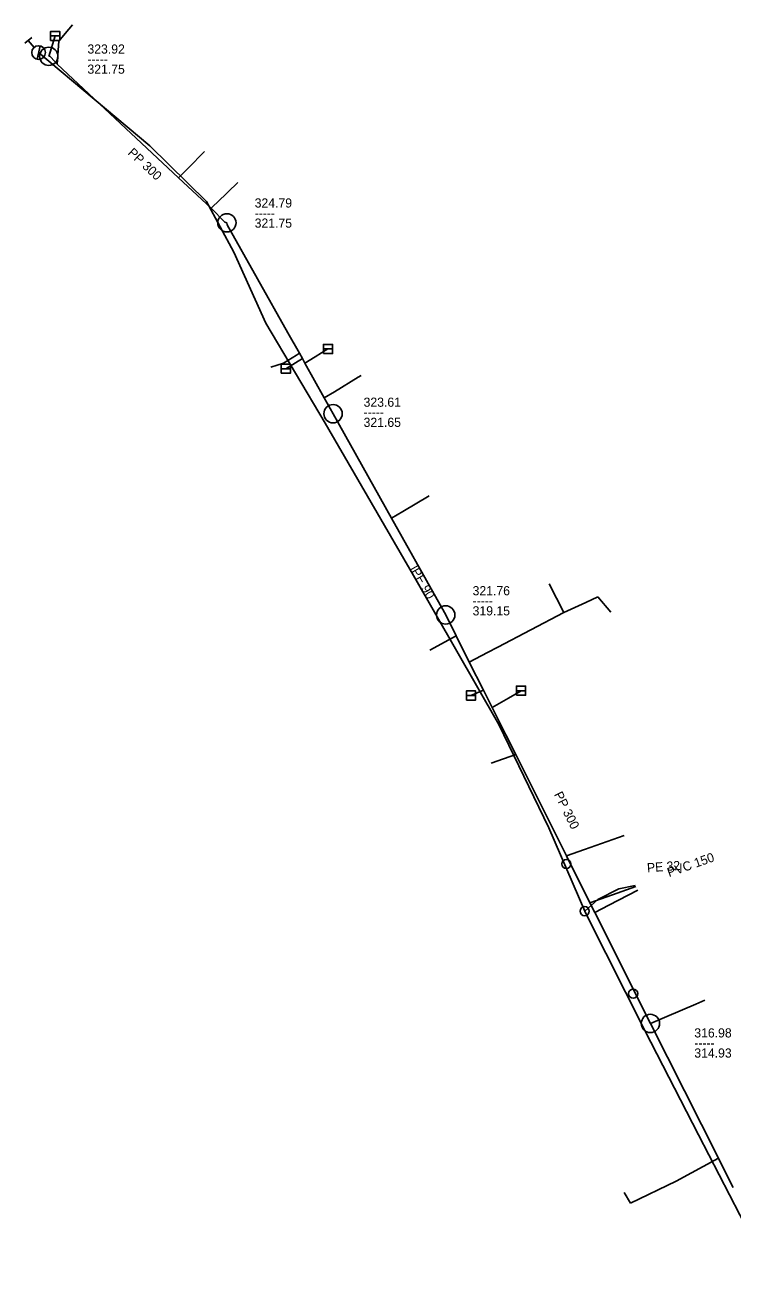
# Model space of a CAD drawing. Extents: x -770550 to -770198, y -1055065 to -1054790.
# Drawn here: x -770439.9 to -770362.5, y -1054925.1 to -1054789.6 of the extents above; entities that cross this region are included whole.
import ezdxf

# ---------------------------------------------------------------- set-up
doc = ezdxf.new("R2010")
doc.units = 0
doc.layers.add('Level 0', color=7, linetype='Continuous')

msp = doc.modelspace()

# ---------------------------------------------------------------- linework, layer by layer
at = {"layer": 'Level 0'}
for p, q in [((-770434.71, -1054789.58), (-770435.51, -1054790.52)), ((-770439.95, -1054791.6), (-770439.18, -1054790.96)), ((-770438.92, -1054792.05), (-770439.56, -1054791.28)), ((-770437.32, -1054793.03), (-770436.62, -1054790.8)), ((-770437.12, -1054790.8), (-770436.12, -1054790.8)), ((-770436.23, -1054791.37), (-770436.4, -1054793.88)), ((-770435.51, -1054790.52), (-770436.23, -1054791.37)), ((-770438.59, -1054793.35), (-770438.28, -1054791.88)), ((-770426.25, -1054802.83), (-770438.44, -1054792.62)), ((-770437.32, -1054793.03), (-770437.24, -1054792.96)), ((-770437.24, -1054792.96), (-770437.09, -1054793.13)), ((-770437.09, -1054793.13), (-770436.4, -1054793.88)), ((-770436.4, -1054793.88), (-770423.11, -1054806.3)), ((-770420.05, -1054808.91), (-770426.25, -1054802.83)), ((-770422.06, -1054805.24), (-770420.28, -1054803.43)), ((-770423.11, -1054806.3), (-770422.06, -1054805.24)), ((-770423.11, -1054806.3), (-770419.56, -1054809.62)), ((-770418.86, -1054808.96), (-770416.63, -1054806.84)), ((-770417.08, -1054814.45), (-770420.05, -1054808.91)), ((-770419.29, -1054809.36), (-770418.86, -1054808.96)), ((-770419.56, -1054809.62), (-770419.29, -1054809.36)), ((-770419.56, -1054809.62), (-770418.06, -1054811.17)), ((-770418.06, -1054811.17), (-770417.83, -1054811.23)), ((-770417.83, -1054811.23), (-770417.8, -1054811.46)), ((-770417.8, -1054811.46), (-770411.15, -1054823.26)), ((-770413.56, -1054822.19), (-770417.08, -1054814.45)), ((-770407.07, -1054833.15), (-770413.56, -1054822.19)), ((-770411.15, -1054823.26), (-770409.89, -1054825.49)), ((-770409.89, -1054825.49), (-770410.21, -1054825.69)), ((-770409.89, -1054825.49), (-770409.57, -1054826.07)), ((-770408.17, -1054825.87), (-770406.77, -1054825.02)), ((-770407.27, -1054825.02), (-770406.27, -1054825.02)), ((-770411.62, -1054826.58), (-770413.02, -1054827.01)), ((-770410.21, -1054825.69), (-770411.62, -1054826.58)), ((-770409.57, -1054826.07), (-770411.38, -1054827.18)), ((-770409.57, -1054826.07), (-770409.29, -1054826.56)), ((-770409.29, -1054826.56), (-770408.17, -1054825.87)), ((-770409.29, -1054826.56), (-770407.17, -1054830.37)), ((-770411.88, -1054827.18), (-770410.88, -1054827.18)), ((-770403.46, -1054828.11), (-770406.04, -1054829.69)), ((-770403.14, -1054827.92), (-770403.46, -1054828.11)), ((-770406.04, -1054829.69), (-770407.17, -1054830.37)), ((-770407.17, -1054830.37), (-770406.21, -1054832.1)), ((-770406.21, -1054832.1), (-770399.81, -1054843.52)), ((-770397.41, -1054849.79), (-770407.07, -1054833.15)), ((-770395.69, -1054841.08), (-770398.57, -1054842.78)), ((-770398.57, -1054842.78), (-770399.81, -1054843.52)), ((-770399.81, -1054843.52), (-770394.83, -1054852.41)), ((-770388.06, -1054866.07), (-770397.41, -1054849.79)), ((-770380.97, -1054853.84), (-770382.58, -1054850.71)), ((-770394.83, -1054852.41), (-770393.88, -1054854.1)), ((-770378.56, -1054852.74), (-770377.23, -1054852.11)), ((-770377.23, -1054852.11), (-770375.82, -1054853.8)), ((-770388.17, -1054857.61), (-770380.97, -1054853.84)), ((-770380.97, -1054853.84), (-770378.56, -1054852.74)), ((-770393.88, -1054854.1), (-770392.73, -1054856.39)), ((-770392.73, -1054856.39), (-770395.62, -1054857.96)), ((-770392.73, -1054856.39), (-770391.3, -1054859.25)), ((-770389.32, -1054858.21), (-770388.17, -1054857.61)), ((-770391.3, -1054859.25), (-770389.32, -1054858.21)), ((-770391.3, -1054859.25), (-770389.76, -1054862.31)), ((-770391.62, -1054862.91), (-770390.62, -1054862.91)), ((-770391.12, -1054862.91), (-770389.76, -1054862.31)), ((-770389.76, -1054862.31), (-770388.8, -1054864.22)), ((-770388.8, -1054864.22), (-770387.02, -1054863.19)), ((-770387.02, -1054863.19), (-770385.64, -1054862.38)), ((-770386.14, -1054862.38), (-770385.14, -1054862.38)), ((-770388.8, -1054864.22), (-770387.31, -1054867.2)), ((-770382.6, -1054877.39), (-770388.06, -1054866.07)), ((-770387.31, -1054867.2), (-770386.22, -1054869.37)), ((-770388.9, -1054870.32), (-770386.22, -1054869.37)), ((-770386.22, -1054869.37), (-770380.68, -1054880.42)), ((-770378.67, -1054886.48), (-770382.6, -1054877.39)), ((-770374.35, -1054878.21), (-770375.61, -1054878.65)), ((-770375.61, -1054878.65), (-770378.71, -1054879.73)), ((-770378.71, -1054879.73), (-770380.68, -1054880.42)), ((-770380.68, -1054880.42), (-770378.11, -1054885.56)), ((-770374.94, -1054884.05), (-770373.16, -1054883.66)), ((-770375.64, -1054884.69), (-770378.11, -1054885.56)), ((-770377.22, -1054885.2), (-770374.94, -1054884.05)), ((-770376.04, -1054885.84), (-770372.85, -1054884.18)), ((-770373.09, -1054883.79), (-770375.64, -1054884.69)), ((-770378.67, -1054886.48), (-770377.22, -1054885.2)), ((-770378.11, -1054885.56), (-770377.57, -1054886.64)), ((-770377.57, -1054886.64), (-770376.04, -1054885.84)), ((-770378.47, -1054886.89), (-770378.67, -1054886.48)), ((-770372.08, -1054899.52), (-770378.47, -1054886.89)), ((-770377.57, -1054886.64), (-770371.48, -1054898.76)), ((-770366.5, -1054896.65), (-770369.68, -1054898)), ((-770365.51, -1054896.23), (-770366.5, -1054896.65)), ((-770369.68, -1054898), (-770371.48, -1054898.76)), ((-770366.23, -1054910.92), (-770372.08, -1054899.52)), ((-770371.48, -1054898.76), (-770364.03, -1054913.49)), ((-770358.93, -1054925.08), (-770366.23, -1054910.92)), ((-770364.03, -1054913.49), (-770368.65, -1054915.99)), ((-770364.03, -1054913.49), (-770363.65, -1054914.24)), ((-770363.65, -1054914.24), (-770362.41, -1054916.7)), ((-770368.65, -1054915.99), (-770373.67, -1054918.41)), ((-770373.67, -1054918.41), (-770374.36, -1054917.25))]:
    msp.add_line(p, q, dxfattribs=at)
for points in [[(-770437.12, -1054791.3), (-770436.12, -1054791.3), (-770436.12, -1054790.3), (-770437.12, -1054790.3)], [(-770407.27, -1054825.52), (-770406.27, -1054825.52), (-770406.27, -1054824.52), (-770407.27, -1054824.52)], [(-770411.88, -1054827.68), (-770410.88, -1054827.68), (-770410.88, -1054826.68), (-770411.88, -1054826.68)], [(-770386.14, -1054862.88), (-770385.14, -1054862.88), (-770385.14, -1054861.88), (-770386.14, -1054861.88)], [(-770391.62, -1054863.41), (-770390.62, -1054863.41), (-770390.62, -1054862.41), (-770391.62, -1054862.41)]]:
    msp.add_lwpolyline(points, close=True, dxfattribs=at)
for centre, radius in [((-770438.44, -1054792.62), 0.75), ((-770437.32, -1054793.03), 1), ((-770417.83, -1054811.23), 1), ((-770406.21, -1054832.1), 1), ((-770393.88, -1054854.1), 1), ((-770380.69, -1054881.32), 0.5), ((-770378.67, -1054886.48), 0.5), ((-770373.37, -1054895.5), 0.5), ((-770371.48, -1054898.76), 1)]:
    msp.add_circle(centre, radius, dxfattribs=at)

# ---------------------------------------------------------------- texts
for s, p in [('323.92', (-770433.09, -1054792.73)), ('321.75', (-770433.09, -1054794.93)), ('-----', (-770433.09, -1054793.83)), ('324.79', (-770414.79, -1054809.56)), ('-----', (-770414.79, -1054810.66)), ('321.75', (-770414.79, -1054811.76)), ('323.61', (-770402.87, -1054831.34)), ('-----', (-770402.87, -1054832.44)), ('321.65', (-770402.87, -1054833.54)), ('321.76', (-770390.94, -1054851.95)), ('319.15', (-770390.94, -1054854.15)), ('-----', (-770390.94, -1054853.05)), ('316.98', (-770366.68, -1054900.29)), ('-----', (-770366.68, -1054901.39)), ('314.93', (-770366.68, -1054902.49))]:
    msp.add_text(s, height=1, dxfattribs=at).set_placement(p)
for s, rotation, p in [('PP 300', 316.938, (-770428.74, -1054803.67)), ('lPE 90', 299.87, (-770397.84, -1054849.06)), ('PP 300', 296.565, (-770382.06, -1054873.71)), ('PE 32', 4.284, (-770371.82, -1054882.24)), ('PVC 150', 19.404, (-770369.44, -1054882.77))]:
    msp.add_text(s, height=1, rotation=rotation, dxfattribs=at).set_placement(p)

doc.saveas('drawing.dxf')
